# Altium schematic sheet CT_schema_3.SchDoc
size 454 x 403 mm
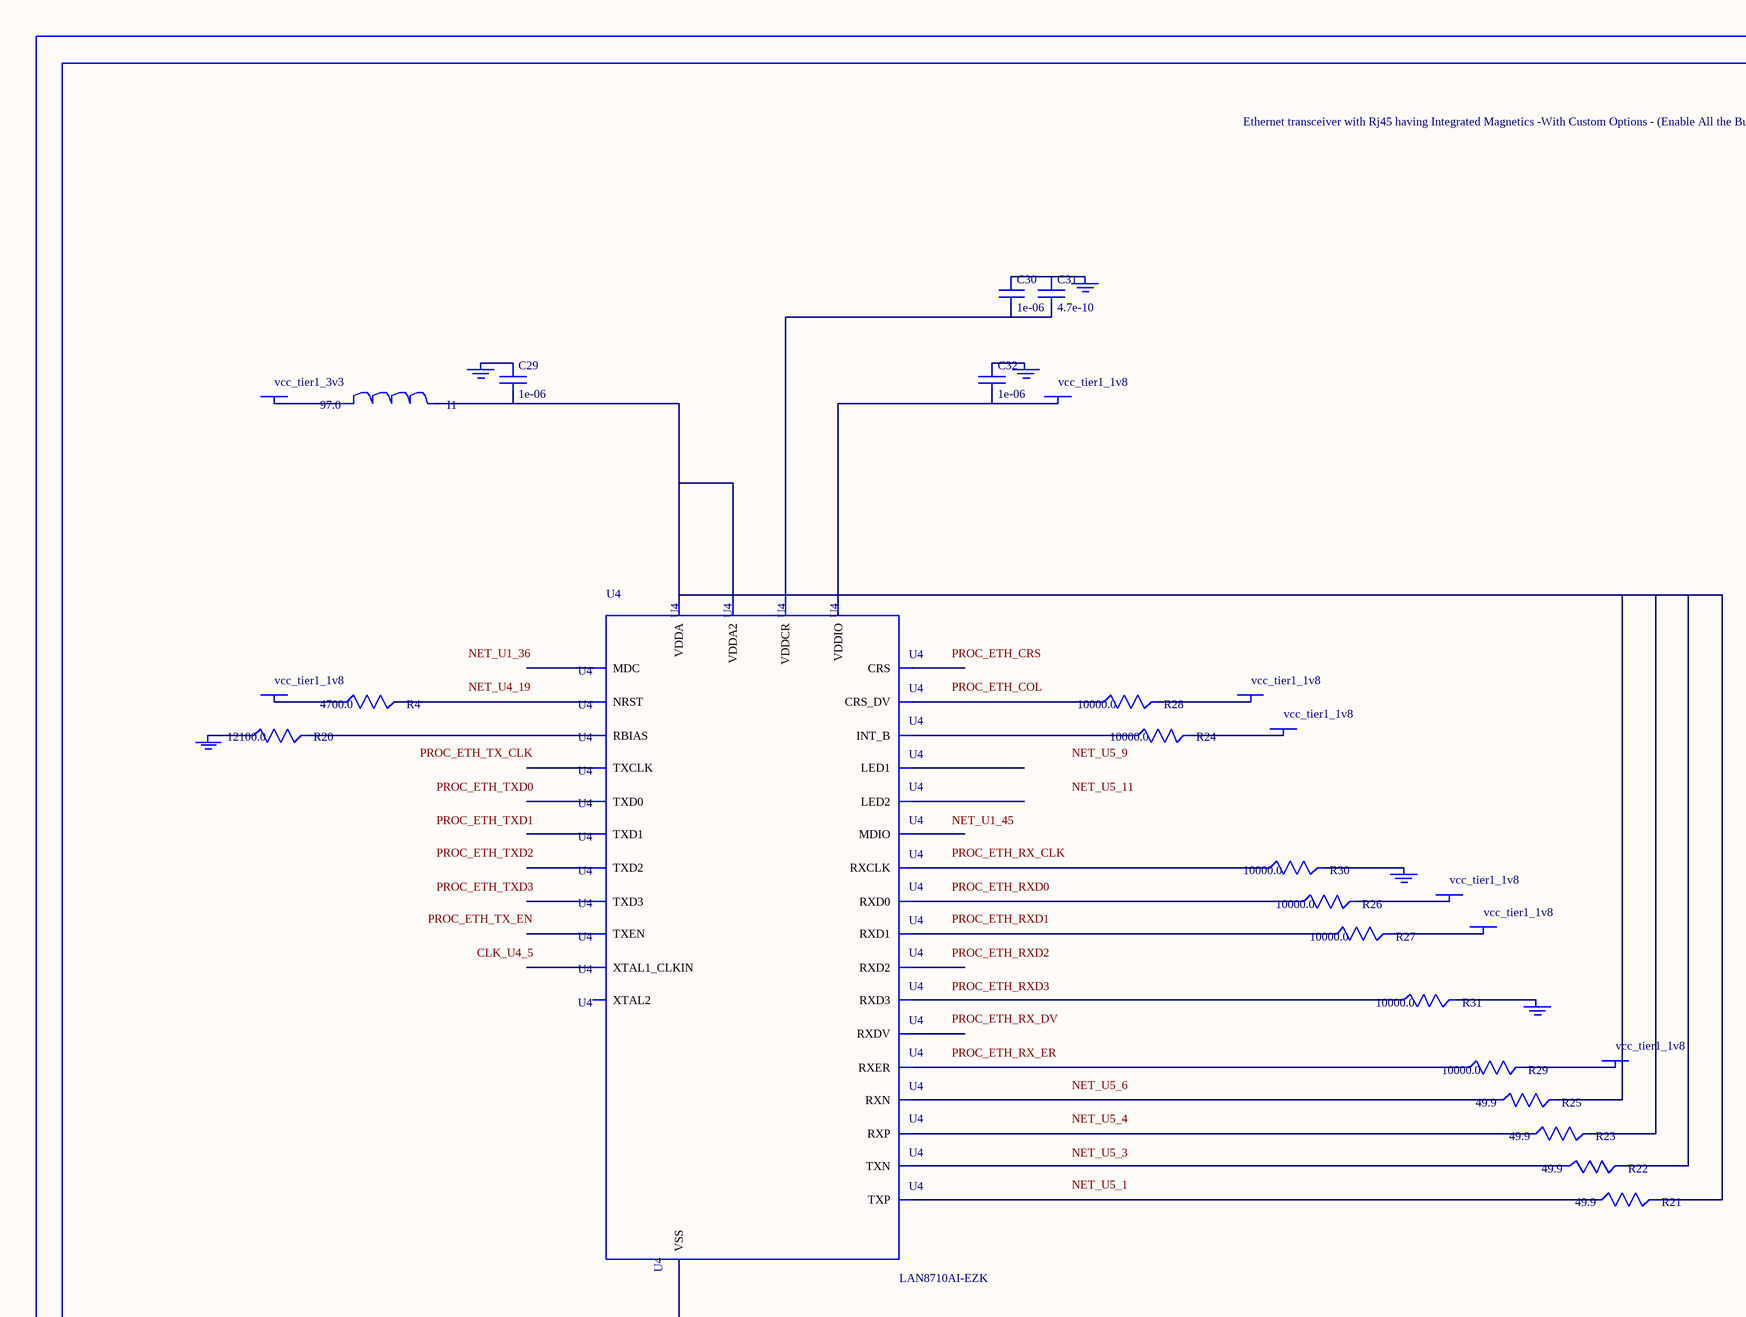
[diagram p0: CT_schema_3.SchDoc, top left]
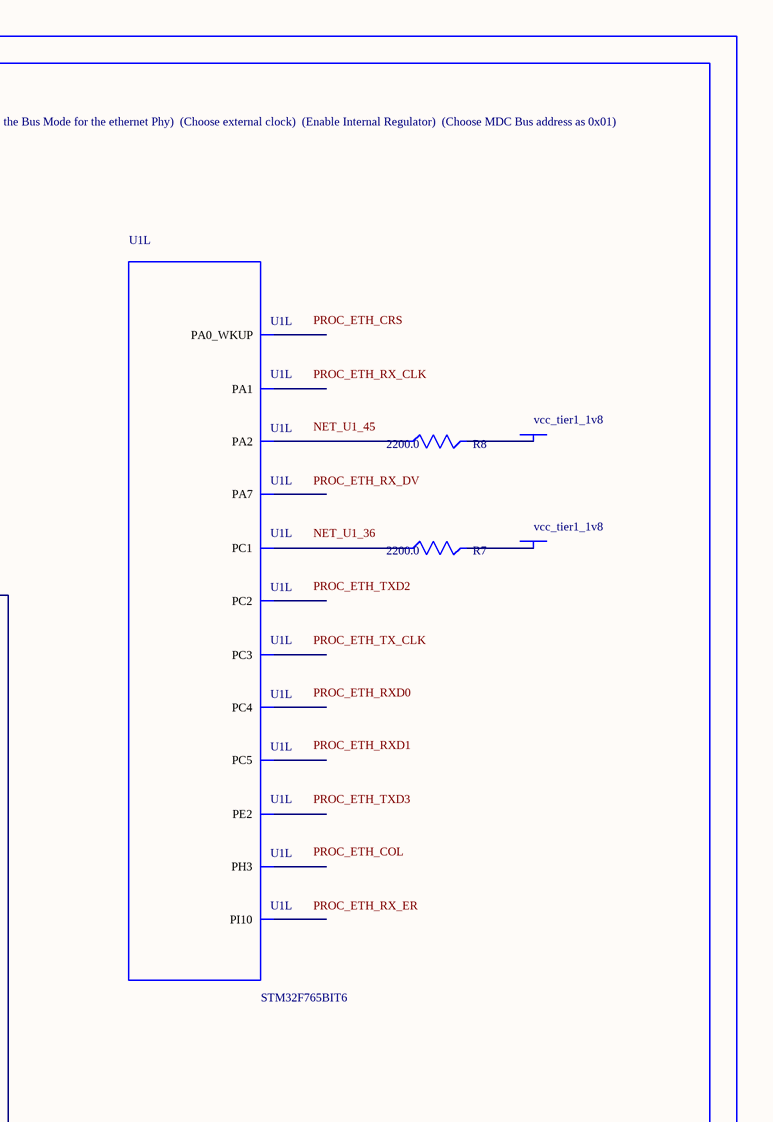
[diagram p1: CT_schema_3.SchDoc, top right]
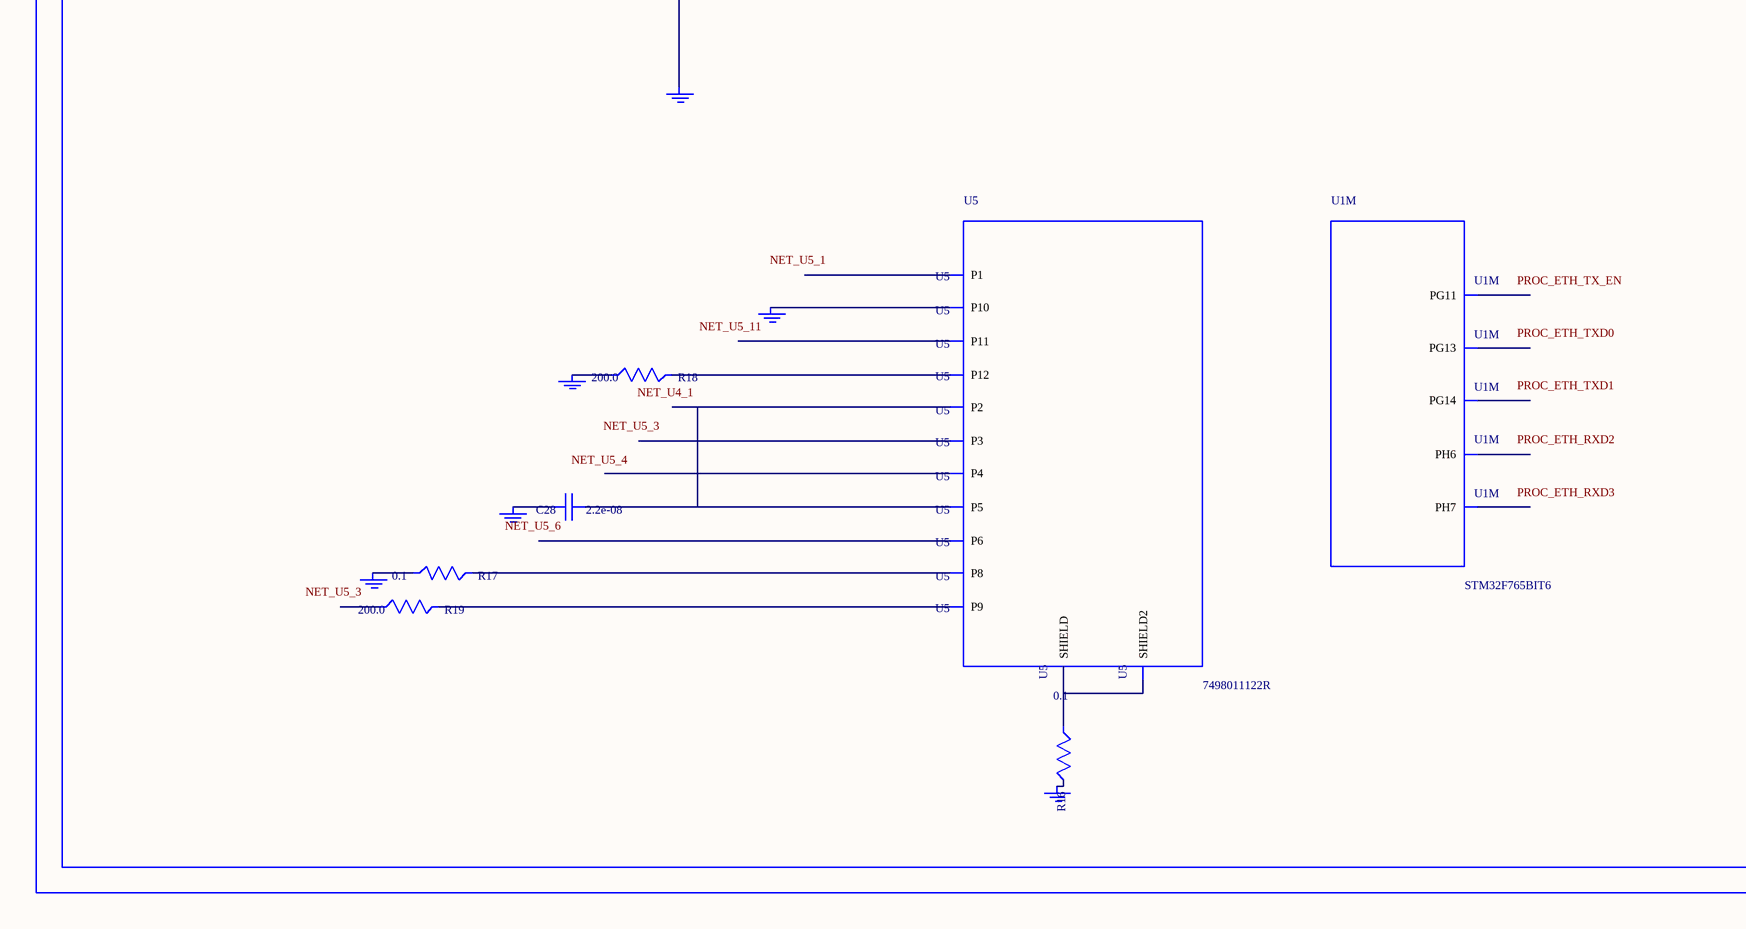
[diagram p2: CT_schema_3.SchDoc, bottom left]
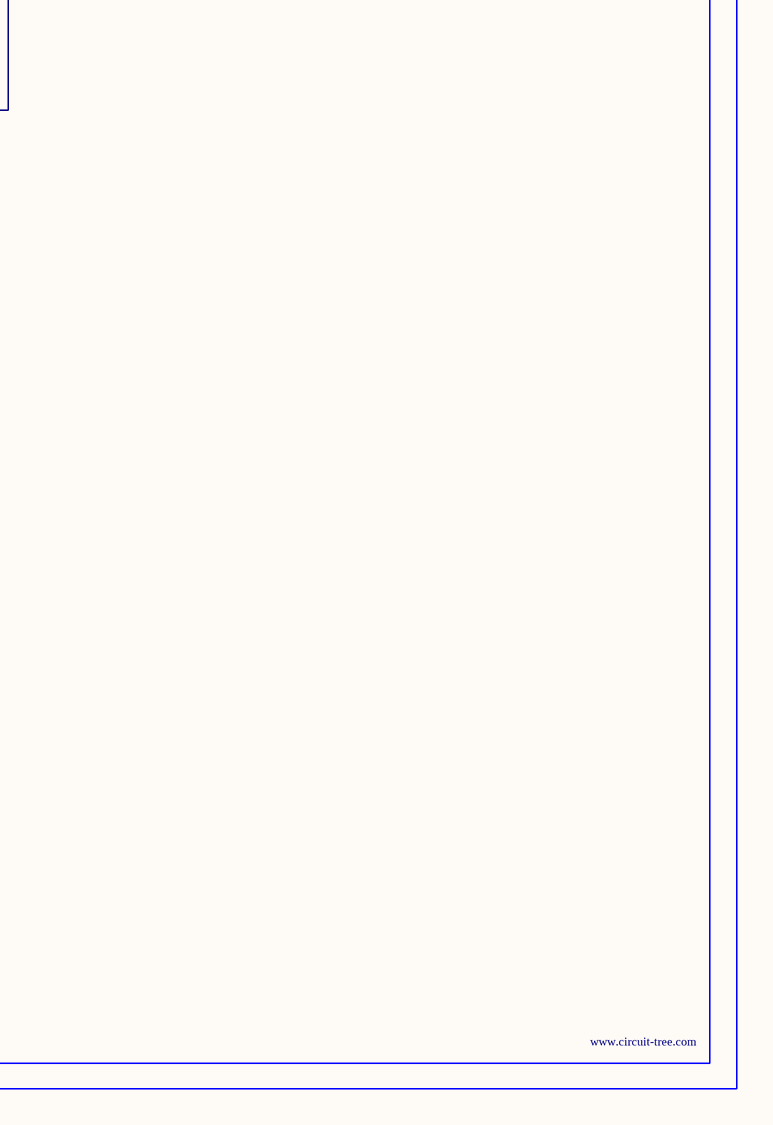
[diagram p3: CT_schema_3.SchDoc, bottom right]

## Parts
BORDER2  (no value)
C28  2.2e-08  [C0402]
C29  1e-06  [C0603]
C30  1e-06  [C0603]
C31  4.7e-10  [C0603]
C32  1e-06  [C0603]
GND_INSTANCE_2_0  (no value)
GND_INSTANCE_2_1  (no value)
GND_INSTANCE_2_2  (no value)
GND_INSTANCE_2_3  (no value)
GND_INSTANCE_2_4  (no value)
GND_INSTANCE_2_5  (no value)
GND_INSTANCE_2_6  (no value)
GND_INSTANCE_2_7  (no value)
GND_INSTANCE_2_8  (no value)
GND_INSTANCE_2_9  (no value)
GND_INSTANCE_2_10  (no value)
GND_INSTANCE_2_11  (no value)
I1  97.0  [R0603]
POWER_INSTANCE_2_0  vcc_tier1_3v3
POWER_INSTANCE_2_1  vcc_tier1_1v8
POWER_INSTANCE_2_2  vcc_tier1_1v8
POWER_INSTANCE_2_3  vcc_tier1_1v8
POWER_INSTANCE_2_4  vcc_tier1_1v8
POWER_INSTANCE_2_5  vcc_tier1_1v8
POWER_INSTANCE_2_6  vcc_tier1_1v8
POWER_INSTANCE_2_7  vcc_tier1_1v8
POWER_INSTANCE_2_8  vcc_tier1_1v8
POWER_INSTANCE_2_9  vcc_tier1_1v8
R4  4700.0  [R0603]
R7  2200.0  [R0603]
R8  2200.0  [R0603]
R16  0.1  [R0603]
R17  0.1  [R0603]
R18  200.0  [R0603]
R19  200.0  [R0603]
R20  12100.0  [R0603]
R21  49.9  [R0603]
R22  49.9  [R0603]
R23  49.9  [R0603]
R24  10000.0  [R0603]
R25  49.9  [R0603]
R26  10000.0  [R0603]
R27  10000.0  [R0603]
R28  10000.0  [R0603]
R29  10000.0  [R0603]
R30  10000.0  [R0603]
R31  10000.0  [R0603]
U1  STM32F765BIT6  [LQFP208]  (parts L,M of 17)
U4  LAN8710AI-EZK  [QFN-32]
U5  7498011122R  [7498011122R]

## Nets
NetC28_1: C28.1 U5.2(P2) U5.5(P5)
NetC28_2: C28.2 GND_INSTANCE_2_7.0(GND)
NetC29_1: C29.1 GND_INSTANCE_2_0.0(GND)
NetC29_2: C29.2 I1.2 R21.2 R22.2 R23.2 R25.2 U4.1(VDDA) U4.27(VDDA2)
NetC30_1: C30.1 C31.1 GND_INSTANCE_2_1.0(GND)
NetC30_2: C30.2 C31.2 U4.6(VDDCR)
NetC32_1: C32.1 GND_INSTANCE_2_4.0(GND)
NetC32_2: C32.2 POWER_INSTANCE_2_3.0(PWR) U4.12(VDDIO)
NetGND_INSTANCE_2_2_0: GND_INSTANCE_2_2.0(GND) R30.2
NetGND_INSTANCE_2_3_0: GND_INSTANCE_2_3.0(GND) R31.2
NetGND_INSTANCE_2_5_0: GND_INSTANCE_2_5.0(GND) R20.1
NetGND_INSTANCE_2_6_0: GND_INSTANCE_2_6.0(GND) U4.EXP(VSS)
NetGND_INSTANCE_2_8_0: GND_INSTANCE_2_8.0(GND) R17.1
NetGND_INSTANCE_2_9_0: GND_INSTANCE_2_9.0(GND) U5.10(P10)
NetGND_INSTANCE_2_10_0: GND_INSTANCE_2_10.0(GND) R18.1
NetGND_INSTANCE_2_11_0: GND_INSTANCE_2_11.0(GND) R16.2
NetI1_1: I1.1 POWER_INSTANCE_2_0.0(PWR)
NetPOWER_INSTANCE_2_1_0: POWER_INSTANCE_2_1.0(PWR) R27.2
NetPOWER_INSTANCE_2_2_0: POWER_INSTANCE_2_2.0(PWR) R26.2
NetPOWER_INSTANCE_2_4_0: POWER_INSTANCE_2_4.0(PWR) R29.2
NetPOWER_INSTANCE_2_5_0: POWER_INSTANCE_2_5.0(PWR) R28.2
NetPOWER_INSTANCE_2_6_0: POWER_INSTANCE_2_6.0(PWR) R24.2
NetPOWER_INSTANCE_2_7_0: POWER_INSTANCE_2_7.0(PWR) R4.1
NetPOWER_INSTANCE_2_8_0: POWER_INSTANCE_2_8.0(PWR) R7.2
NetPOWER_INSTANCE_2_9_0: POWER_INSTANCE_2_9.0(PWR) R8.2
NetR4_2: R4.2 U4.19(NRST)
NetR7_1: R7.1 U1.36(PC1)
NetR8_1: R8.1 U1.45(PA2)
NetR16_1: R16.1 U5.13(SHIELD) U5.14(SHIELD2)
NetR17_2: R17.2 U5.8(P8)
NetR18_2: R18.2 U5.12(P12)
NetR19_2: R19.2 U5.9(P9)
NetR20_2: R20.2 U4.32(RBIAS)
NetR21_1: R21.1 U4.29(TXP)
NetR22_1: R22.1 U4.28(TXN)
NetR23_1: R23.1 U4.31(RXP)
NetR24_1: R24.1 U4.18(INT_B)
NetR25_1: R25.1 U4.30(RXN)
NetR26_1: R26.1 U4.11(RXD0)
NetR27_1: R27.1 U4.10(RXD1)
NetR28_1: R28.1 U4.15(CRS_DV)
NetR29_1: R29.1 U4.13(RXER)
NetR30_1: R30.1 U4.7(RXCLK)
NetR31_1: R31.1 U4.8(RXD3)

Not connected (* = marked no-connect by the designer): R19 1; U1 1(PE2) 12(PI10) 37(PC2) 38(PC3) 43(PA0_WKUP) 44(PA1) 47(PH3) 56(PA7) 57(PC4) 58(PC5) 96(PH6) 97(PH7) 180(PG11) 182(PG13) 183(PG14); U4 2(LED2) 3(LED1) 4(XTAL2) 5(XTAL1_CLKIN) 9(RXD2) 14(CRS) 16(MDIO) 17(MDC) 20(TXCLK) 21(TXEN) 22(TXD0) 23(TXD1) 24(TXD2) 25(TXD3) 26(RXDV); U5 1(P1) 3(P3) 4(P4) 6(P6) 11(P11)

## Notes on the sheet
- Labels drawn without touching a wire or pin: CLK_U4_5, NET_U1_36, NET_U1_45, NET_U4_1, NET_U4_19, NET_U5_1, NET_U5_3, NET_U5_4, NET_U5_6, NET_U5_9, NET_U5_11, PROC_ETH_COL, PROC_ETH_CRS, PROC_ETH_RX_CLK, PROC_ETH_RX_DV, PROC_ETH_RX_ER, PROC_ETH_RXD0, PROC_ETH_RXD1, PROC_ETH_RXD2, PROC_ETH_RXD3, PROC_ETH_TX_CLK, PROC_ETH_TX_EN, PROC_ETH_TXD0, PROC_ETH_TXD1, PROC_ETH_TXD2, PROC_ETH_TXD3

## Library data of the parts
BORDER2 = BORDER_PAGE2
C28 = C0402C223K3RAC
C29 C30 C32 = C0603C105K3RACTU
C31 = 06031C471KAZ2A
GND_INSTANCE_2_0-GND_INSTANCE_2_11 = GND
I1 = I1
POWER_INSTANCE_2_0-POWER_INSTANCE_2_9 = PWR
R4 = RC0603JR-074K7L
R7 R8 = RC0603JR-072K2L
R16 R17 = ERJ-3RSFR10V
R18 R19 = RC0603JR-07200RL
R20 = TNPW060312K1BEEA
R21-R23 R25 = RC0603FR-0749R9L
R24 R26-R31 = RC0603JR-0710KL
